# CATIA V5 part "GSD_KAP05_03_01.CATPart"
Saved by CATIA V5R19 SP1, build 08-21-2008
Part number: GSD_EXTREMUM_01
Definition: Beispielmodell: Äußerster Punkt
Description: CATIA V5 Flächenmodellierung  Copyright (c) 2009 Maik Hertha IT Consultants
Bounding box of the stored display mesh (mm): x -49.823 to 32.138, y -13.595 to 66.381, z 0 to 59.237
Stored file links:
  \GSD_BUCH_UEBUNG\GSD_KAP05_03_01.CATPart
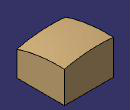
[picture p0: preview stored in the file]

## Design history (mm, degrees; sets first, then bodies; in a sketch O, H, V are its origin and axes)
AxisSystem1 "Absolute Axis System": origin (0, 0, 0), X (1, 0, 0), Y (0, 1, 0), Z (0, 0, 1)
Set1 "Geometrisches Set.1"
  Set2 "Koerper.1"
    Sketch1 on XY plane of AxisSystem1, origin (0, 0, 0), H (1, 0, 0), V (0, 1, 0)
      line L1 (-49.823, 66.3812) -> (32.138, 66.3812)
      line L2 (32.138, 66.3812) -> (32.138, -13.595)
      line L3 (32.138, -13.595) -> (-49.823, -13.595)
      line L4 (-49.823, -13.595) -> (-49.823, 66.3812)
      curve C1
      horizontal: L1 H, L3 H
      vertical: L2 V, L4 V
    Extrude1: Lim1 63, Lim2 0, Element1 Sketch1.C1, Direction (0, 0, 1)
  Set3 "Splitflaeche.1"
    Plane1: stored without definition
    Curve1: Elements ({point type OnPlane, Support YZ plane of AxisSystem1, Direction edge [YZ plane of AxisSystem1 | XY plane of AxisSystem1], H -36.567, V 38.289, RefPoint vertex [YZ plane of AxisSystem1 | ZX plane of AxisSystem1 | XY plane of AxisSystem1]}; {point type OnPlane, Support YZ plane of AxisSystem1, Direction edge [YZ plane of AxisSystem1 | XY plane of AxisSystem1], H 7.775, V 52.817, RefPoint vertex [YZ plane of AxisSystem1 | ZX plane of AxisSystem1 | XY plane of AxisSystem1]}; {point type OnPlane, Support YZ plane of AxisSystem1, Direction edge [YZ plane of AxisSystem1 | XY plane of AxisSystem1], H 116.061, V 50.476, RefPoint vertex [YZ plane of AxisSystem1 | ZX plane of AxisSystem1 | XY plane of AxisSystem1]})
    Curve2: Elements ({point type OnPlane, Support ZX plane of AxisSystem1, Direction edge [ZX plane of AxisSystem1 | YZ plane of AxisSystem1], H 20.048, V 48.407, RefPoint vertex [YZ plane of AxisSystem1 | ZX plane of AxisSystem1 | XY plane of AxisSystem1]}; {point type OnPlane, Support ZX plane of AxisSystem1, Direction edge [ZX plane of AxisSystem1 | YZ plane of AxisSystem1], H 31.514, V -4.936, RefPoint vertex [YZ plane of AxisSystem1 | ZX plane of AxisSystem1 | XY plane of AxisSystem1]}; {point type OnPlane, Support ZX plane of AxisSystem1, Direction edge [ZX plane of AxisSystem1 | YZ plane of AxisSystem1], H 25.781, V -79.225, RefPoint vertex [YZ plane of AxisSystem1 | ZX plane of AxisSystem1 | XY plane of AxisSystem1]})
    DatumSurface1 "X-Profile.1"
  Trim1: Element1 Extrude1, Element2 DatumSurface1
Body1 (main body)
